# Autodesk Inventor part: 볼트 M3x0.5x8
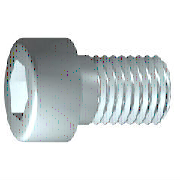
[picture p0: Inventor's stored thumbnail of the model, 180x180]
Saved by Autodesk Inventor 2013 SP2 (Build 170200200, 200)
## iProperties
IsCustomPart: 1
Company: 한국ATC센터
Created: 2015-12
Part Number: 볼트 M3x0.5x8
Material: 스테인리스강
Description: 6각머리 태핑 나사
Document SubType Name: Modeling
Standard: KS B 1003
Designer: mdu
Standards Organization: KS
Language: ko-KR
Size Designation: M 4 x 12
Categories: <MemberInstance><Categories><Category DisplayName="조임쇠" InternalName="e4da775c-781d-43d5-af7c-5136215cf5a6" Mnemonic="FSTN"><Category DisplayName="볼트" InternalN
Density: 8.08 g/cm^3
Mass: 1.41278 g
Surface Area: 2.584 cm^2
Volume: 0.174849 cm^3
Author: mdu
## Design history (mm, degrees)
sketch "스케치1"
  geometry: L1 (-0.867, 0)-(16, 0); L2 (16, 0)-(16, 1.5); L3 (16, 1.5)-(1.25, 1.5); L4 (1.25, 1.5)-(0.943, 1.5); L5 (0.943, 1.5)-(0, 1.5); L6 (0, 1.5)-(0, 2.75); L7 (0, 2.75)-(-3, 2.75); L8 (-3, 2.75)-(-3, 1.443); L9 (-3, 1.443)-(-1.7, 1.443); L10 (-1.7, 1.443)-(-0.867, 0); L11 (-6.8, 0)-(19.8, 0) reference; L12 (0, -0.55)-(0, 3.3) reference; L13 (1.25, 1.5)-(0, 1.5)
  constraints: 22 end point, 6 parallel, 2 collinear, 2 perpendicular, 1 horizontal, 1 point on line
  dimensions: "d1" = 14.75 distance from line of L3.end L2 (= GEL); "d2" = 0.30683 distance of L4.end L3.end (computed from GAL); "d3" = 3 distance between parallel lines of L8 L6 (= KOH); "d4" = 1.3 distance of L8.end L9.end (= INTI); "d5" = 60 deg angle of L10 L1; "d6" = 3 diameter of L3 L1 (= GD); "d7" = 3 diameter of L5 L1 (= BDM); "d8" = 2.88675 diameter of L9 L1 (= 1.1547 x SW); "d9" = 5.5 diameter of L7 L1 (= KOD); "d26" = 16 distance between parallel lines of L12 L2 (= NLG)
revolve "본체" sketch "스케치1" stored, may be unused: angle "d10" = 90 deg
sketch "스케치2"
  geometry: L1 (0, -3.85)-(0, 3.85) reference; L2 (-3.85, 0)-(3.85, 0) reference; L3 (1.443, 0)-(0.722, -1.25); L4 (0.722, -1.25)-(-0.722, -1.25); L5 (-0.722, -1.25)-(-1.443, 0); L6 (-1.443, 0)-(-0.722, 1.25); L7 (-0.722, 1.25)-(0.722, 1.25); L8 (0.722, 1.25)-(1.443, 0); 2 further points
  constraints: 12 end point, 1 coincident, 1 horizontal alignment, 1 point on line, 12 other
extrude "슬롯" join sketch "스케치2" stored distance "d11" = 10; taper "d12" = 0 deg
workplane "Work Plane1"
fillet "Fillet2" dims "d30" = 0.1 (= R)
body "Solid1"
fillet "모깎기1" dims "d17" = 0.3 (= RR)
feature "스레드" dims "d13" = 14.75 (= GEL), "d14" = 0
chamfer "모따기1" distance "d15" = 0.30673 (= -0.5 x SPD + 0.5 x GD); stored, may be unused: second distance "d16" = 0.30673 (= GUL), angle "d27" = 45 deg
other parameters: "GD" = 3 (= NND) [user parameter; used in 2 equation terms], "NLG" = 16 [user parameter; used in 1 equation term], "GEL" = 14.75 [user parameter; used in 2 equation terms], "KOD" = 5.5 [user parameter; used in 1 equation term], "KOH" = 3 [user parameter; used in 1 equation term], "INTI" = 1.3 [user parameter; used in 1 equation term], "GAL" = 0.30673 (= 0.61345 x PTC) [user parameter; used in 1 equation term], "GUL" = 0.30673 (= 0.61345 x PTC) [user parameter; used in 1 equation term], "BDM" = 3 (= NND) [user parameter; used in 1 equation term], "SW" = 2.5 [user parameter; used in 2 equation terms], "RR" = 0.3 [user parameter; used in 1 equation term], "SPD" = 2.38655 (= NND - 1.2269 x PTC) [user parameter; used in 1 equation term], "d19" = 0, "d28" = 0, "d29" = 0, "R" = 0.1 [user parameter; used in 1 equation term], "PHH" = 0.1 [user parameter], "GD1" = 2.38655 (= THREADDIA - 1.2269 x PTC) [user parameter], "THREADDIA" = 3 [user parameter; used in 1 equation term], "FAWI" = 45 deg [user parameter], "PTC" = 0.5 [user parameter; used in 5 equation terms], "NND" = 3 [user parameter; used in 3 equation terms], "TOA" = 30 deg [user parameter], "E0" = 2.8875 (= 1.155 x SW) [user parameter]
